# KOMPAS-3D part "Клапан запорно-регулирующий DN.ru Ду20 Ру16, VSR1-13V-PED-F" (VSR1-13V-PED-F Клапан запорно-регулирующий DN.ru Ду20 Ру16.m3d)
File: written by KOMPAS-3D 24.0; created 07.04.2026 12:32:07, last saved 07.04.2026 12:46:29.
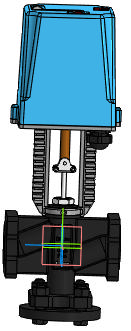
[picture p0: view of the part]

Document properties: Автор: R2D2; Полное имя файла: E:\Работа\Зайцев\Солянка\VSR1-13V-PED-F Клапан запорно-регулирующий DN.ru\DN20\VSR1-13V-PED-F Клапан запорно-регулирующий DN.ru Ду20 Ру16.m3d

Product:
- Body: Тело 2  | qty 1
    Масса: 21.746757
- Part/product: Клапан запорно-регулирующий DN.ru Ду20 Ру16  | designation VSR1-13V-PED-F
    Масса: 6.9
    Раздел спецификации: Прочие изделия
    Примечание: D090-02887

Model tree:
1. Операция без истории:1  (labels: SHAPEOBJECT3D_ATTR_BUTT)

Expressions: VSR1-13V-PED-F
